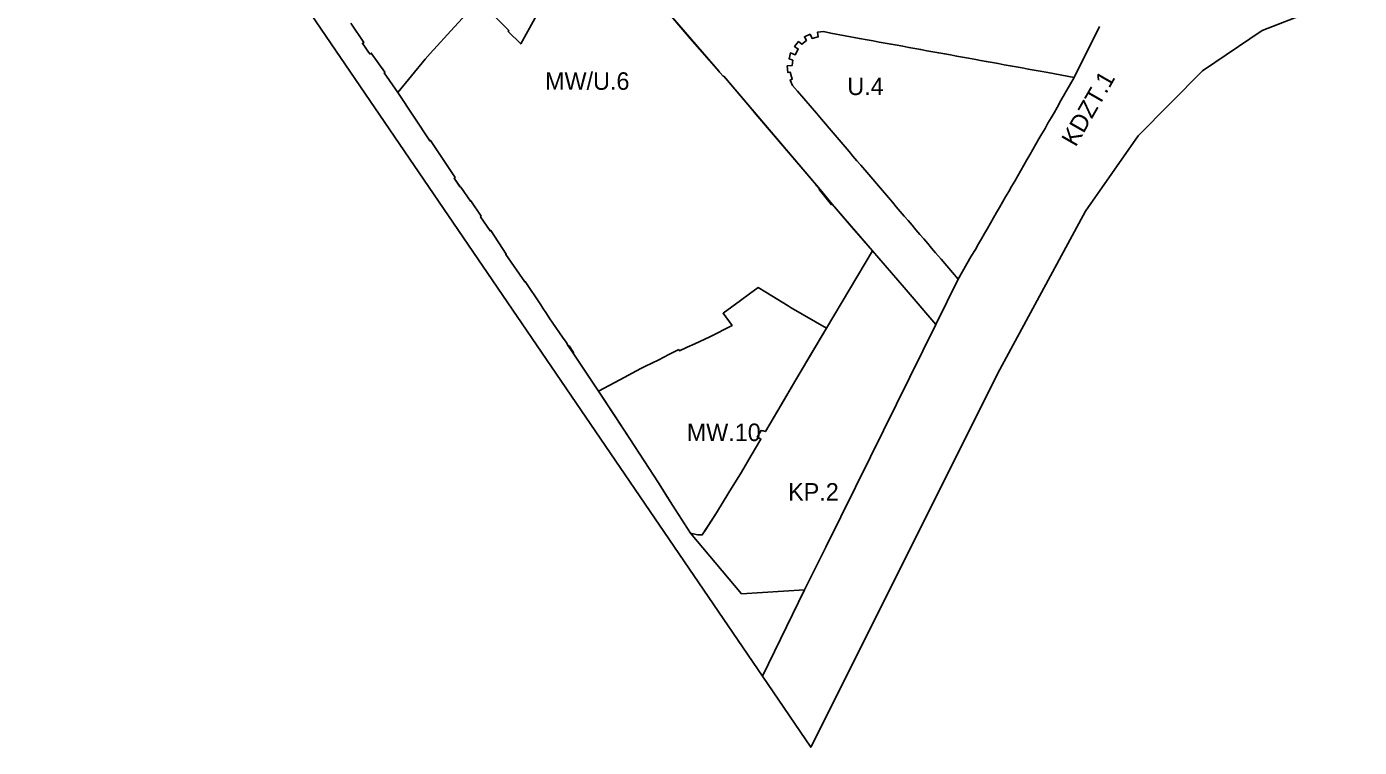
# Model space of a CAD drawing. Extents: x 7423893 to 7425332, y 5547241 to 5548246.
# Drawn here: x 7424259.3 to 7424640.4, y 5547241.4 to 5547447.3 of the extents above; entities that cross this region are included whole.
import ezdxf

# ---------------------------------------------------------------- set-up
doc = ezdxf.new("R2010")
doc.units = 0
for name, color, linetype in [('linie rozgraniczające', 7, 'Continuous'), ('obowiazujace linie zabudowy', 7, 'Continuous'), ('przeznaczenia terenów', 7, 'Continuous')]:
    doc.layers.add(name, color=color, linetype=linetype)

msp = doc.modelspace()

# ---------------------------------------------------------------- linework, layer by layer
at = {"layer": 'linie rozgraniczające'}
for p, q in [((7424566.05, 5547447.44), (7424558.82, 5547432.87)), ((7424525.63, 5547375.18), (7424519.23, 5547362.27)), ((7424469.69, 5547261.72), (7424469.69, 5547261.72))]:
    msp.add_line(p, q, dxfattribs=at)
for points in [[(7424259.33, 5547570.21), (7424469.69, 5547261.72)], [(7424469.69, 5547261.72), (7424483.52, 5547241.43), (7424537.6, 5547349.36), (7424562.07, 5547394.62), (7424577.11, 5547416.18), (7424595.5, 5547434.76), (7424612.59, 5547446.29), (7424626.63, 5547451.7), (7424635.53, 5547459.94), (7424639.81, 5547463.89), (7424640.36, 5547480.81)], [(7424415.66, 5547470.19), (7424413.19, 5547466.17), (7424409.66, 5547459.31), (7424406.13, 5547452.45), (7424400.58, 5547442.44), (7424397.01, 5547445.97), (7424397.17, 5547446.22), (7424388.59, 5547454.83), (7424381.66, 5547447.26)], [(7424501.13, 5547383.3), (7424489.66, 5547396.63), (7424486.16, 5547400.86), (7424485.17, 5547402.05), (7424467.84, 5547422.39), (7424466.57, 5547423.89), (7424458.65, 5547433.22), (7424458.53, 5547433.13), (7424457.55, 5547434.22), (7424457.44, 5547434.34), (7424457.28, 5547434.51), (7424440.89, 5547453.46)], [(7424351.98, 5547448.38), (7424355.74, 5547442.87), (7424355.32, 5547442.58), (7424355.74, 5547442.02), (7424357.09, 5547440.11), (7424357.53, 5547439.53), (7424357.87, 5547439.79), (7424361.77, 5547434.31), (7424361.56, 5547434.17), (7424365.41, 5547428.52), (7424374.58, 5547414.69), (7424374.81, 5547414.86), (7424381.84, 5547404.24), (7424381.53, 5547404.03), (7424383.1, 5547401.77), (7424383.24, 5547401.57), (7424383.3, 5547401.62), (7424383.42, 5547401.46), (7424386.19, 5547397.46), (7424386.34, 5547397.56), (7424389.26, 5547393.16), (7424389.05, 5547393.01), (7424391.85, 5547388.98), (7424392.05, 5547389.12), (7424396.45, 5547382.37), (7424396.31, 5547382.27), (7424401.76, 5547374.41), (7424401.9, 5547374.51), (7424406.33, 5547367.86), (7424406.92, 5547366.89), (7424407.95, 5547365.35), (7424408.77, 5547364.15), (7424409.79, 5547362.62), (7424410.64, 5547361.36), (7424411.66, 5547359.84), (7424412.5, 5547358.59), (7424413.54, 5547357.17), (7424414.16, 5547356.14), (7424415.61, 5547354.02), (7424422.85, 5547343.23), (7424431.82, 5547329.6), (7424439.96, 5547316.96), (7424444, 5547310.62), (7424447.4, 5547305.27), (7424449.09, 5547302.6), (7424463.74, 5547285.3)], [(7424381.66, 5547447.26), (7424374.72, 5547439.69), (7424373.27, 5547438.11), (7424369.34, 5547433.32), (7424365.41, 5547428.52)], [(7424501.13, 5547383.3), (7424494.58, 5547372.26), (7424488.04, 5547361.23), (7424479.29, 5547346.48), (7424470.55, 5547331.72), (7424469.94, 5547331.84), (7424469.33, 5547331.97), (7424468.78, 5547331.04), (7424468.23, 5547330.1), (7424468.74, 5547329.79), (7424469.25, 5547329.49), (7424466.46, 5547324.79), (7424463.67, 5547320.1), (7424460.13, 5547314.25), (7424456.59, 5547308.39), (7424455.07, 5547306.03), (7424453.55, 5547303.67), (7424452.5, 5547302.12), (7424451.2, 5547302.15), (7424449.88, 5547302.42), (7424449.09, 5547302.6)], [(7424501.13, 5547383.3), (7424510.18, 5547372.79), (7424519.23, 5547362.27), (7424500.59, 5547324.48), (7424487.87, 5547298.59), (7424481.73, 5547286.39), (7424463.74, 5547285.3)], [(7424488.04, 5547361.23), (7424477.93, 5547367.05), (7424477.05, 5547367.56), (7424470.64, 5547371.5), (7424468.5, 5547372.82), (7424465.99, 5547370.98), (7424463.47, 5547369.15), (7424458.44, 5547365.47), (7424461, 5547361.97), (7424454.7, 5547358.77), (7424450.33, 5547356.77), (7424448.15, 5547355.77), (7424445.97, 5547354.77), (7424445.84, 5547355.06)], [(7424445.84, 5547355.06), (7424442.96, 5547353.63), (7424440.08, 5547352.2), (7424438.06, 5547351.23), (7424436.04, 5547350.25), (7424434.91, 5547349.65), (7424428.88, 5547346.44), (7424422.85, 5547343.23)], [(7424469.69, 5547261.72), (7424481.73, 5547286.39)]]:
    msp.add_lwpolyline(points, dxfattribs=at)
msp.add_lwpolyline([(7424506.84, 5547397.21), (7424505.7, 5547398.54), (7424504.57, 5547399.86), (7424503.46, 5547401.16), (7424502.32, 5547402.49), (7424501.22, 5547403.78), (7424500.1, 5547405.1), (7424498.97, 5547406.42), (7424497.84, 5547407.75), (7424496.73, 5547409.05), (7424495.59, 5547410.38), (7424494.5, 5547411.67), (7424493.34, 5547413.02), (7424492.2, 5547414.36), (7424491.06, 5547415.69), (7424489.95, 5547416.99), (7424488.82, 5547418.31), (7424487.74, 5547419.58), (7424486.59, 5547420.92), (7424485.13, 5547422.67), (7424479.75, 5547428.95), (7424478.31, 5547430.5), (7424477.59, 5547432.07), (7424478.22, 5547432.31), (7424477.62, 5547434.36), (7424476.98, 5547434.23), (7424476.8, 5547436.12), (7424478.18, 5547436.23), (7424478.38, 5547437.74), (7424477.3, 5547438.17), (7424477.71, 5547439.83), (7424479.03, 5547439.3), (7424479.96, 5547440.93), (7424478.9, 5547441.73), (7424480.01, 5547443.1), (7424480.98, 5547442.35), (7424482.26, 5547443.42), (7424481.7, 5547444.46), (7424483.31, 5547445.2), (7424483.9, 5547443.97), (7424485.62, 5547444.44), (7424485.46, 5547445.81), (7424487.19, 5547445.95), (7424489.26, 5547445.48), (7424497.41, 5547443.94), (7424499.65, 5547443.58), (7424501.38, 5547443.26), (7424503.07, 5547442.96), (7424504.78, 5547442.65), (7424506.47, 5547442.34), (7424508.18, 5547442.04), (7424509.86, 5547441.74), (7424511.57, 5547441.43), (7424513.26, 5547441.12), (7424514.97, 5547440.8), (7424516.69, 5547440.49), (7424518.4, 5547440.18), (7424520.1, 5547439.87), (7424521.81, 5547439.56), (7424523.5, 5547439.26), (7424525.22, 5547438.95), (7424526.89, 5547438.64), (7424528.61, 5547438.33), (7424530.71, 5547437.95), (7424532.06, 5547437.7), (7424533.71, 5547437.41), (7424535.43, 5547437.1), (7424537.12, 5547436.79), (7424538.85, 5547436.47), (7424540.55, 5547436.17), (7424542.27, 5547435.85), (7424543.96, 5547435.55), (7424545.68, 5547435.24), (7424547.41, 5547434.92), (7424549.12, 5547434.61), (7424551.31, 5547434.22), (7424558.82, 5547432.87), (7424555.06, 5547426.23), (7424553.95, 5547424.27), (7424553.07, 5547422.74), (7424552.23, 5547421.28), (7424551.34, 5547419.73), (7424550.49, 5547418.28), (7424549.6, 5547416.73), (7424548.76, 5547415.27), (7424547.88, 5547413.73), (7424547.04, 5547412.27), (7424546.16, 5547410.74), (7424545.3, 5547409.26), (7424544.42, 5547407.73), (7424543.58, 5547406.27), (7424542.69, 5547404.73), (7424541.84, 5547403.25), (7424540.95, 5547401.71), (7424540.11, 5547400.25), (7424539.22, 5547398.72), (7424538.38, 5547397.24), (7424537.5, 5547395.72), (7424536.65, 5547394.26), (7424535.77, 5547392.72), (7424534.92, 5547391.25), (7424534.03, 5547389.71), (7424533.19, 5547388.25), (7424532.32, 5547386.74), (7424531.47, 5547385.26), (7424530.57, 5547383.7), (7424529.4, 5547381.73), (7424525.63, 5547375.18), (7424520.76, 5547380.92), (7424519.2, 5547382.71), (7424518.07, 5547384.04), (7424516.95, 5547385.35), (7424515.82, 5547386.68), (7424514.7, 5547387.98), (7424513.57, 5547389.3), (7424512.46, 5547390.61), (7424511.33, 5547391.94), (7424510.21, 5547393.24), (7424509.09, 5547394.56), (7424507.96, 5547395.88)], close=True, dxfattribs=at)
at = {"layer": 'obowiazujace linie zabudowy'}
for points in [[(7424456.59, 5547308.39), (7424460.13, 5547314.25), (7424463.67, 5547320.1), (7424466.46, 5547324.79), (7424469.25, 5547329.49), (7424468.74, 5547329.79), (7424468.23, 5547330.1), (7424469.33, 5547331.97), (7424470.55, 5547331.72), (7424474.92, 5547339.1), (7424479.29, 5547346.48), (7424483.67, 5547353.85), (7424488.04, 5547361.23), (7424494.58, 5547372.26), (7424501.13, 5547383.3), (7424495.4, 5547389.96), (7424489.66, 5547396.63), (7424489.47, 5547396.47), (7424485.98, 5547400.7), (7424485.88, 5547400.81), (7424485.98, 5547400.9), (7424485.05, 5547401.96), (7424485.17, 5547402.05), (7424458.65, 5547433.22), (7424458.53, 5547433.13), (7424457.55, 5547434.22), (7424457.44, 5547434.34), (7424457.28, 5547434.51), (7424449.08, 5547443.99), (7424440.89, 5547453.46)], [(7424351.98, 5547448.38), (7424355.74, 5547442.87), (7424355.32, 5547442.58), (7424355.74, 5547442.02), (7424357.09, 5547440.11), (7424357.53, 5547439.53), (7424357.87, 5547439.79), (7424361.77, 5547434.31), (7424361.56, 5547434.17), (7424365.41, 5547428.52), (7424374.58, 5547414.69), (7424374.81, 5547414.86)], [(7424374.81, 5547414.86), (7424381.84, 5547404.24), (7424381.53, 5547404.03), (7424383.24, 5547401.57), (7424383.3, 5547401.62), (7424383.42, 5547401.46), (7424386.19, 5547397.46), (7424386.34, 5547397.56), (7424389.26, 5547393.16), (7424389.05, 5547393.01), (7424391.85, 5547388.98), (7424392.05, 5547389.12), (7424396.45, 5547382.37), (7424396.31, 5547382.27), (7424401.76, 5547374.41), (7424401.9, 5547374.51), (7424406.33, 5547367.86), (7424406.92, 5547366.89), (7424407.95, 5547365.35), (7424408.77, 5547364.15), (7424409.79, 5547362.62), (7424410.64, 5547361.36), (7424411.66, 5547359.84), (7424412.5, 5547358.59), (7424413.54, 5547357.17), (7424414.16, 5547356.14), (7424414.4, 5547356.14), (7424415.69, 5547354.23), (7424415.61, 5547354.02), (7424422.85, 5547343.23), (7424427.33, 5547336.42), (7424431.82, 5547329.6), (7424435.89, 5547323.28), (7424439.96, 5547316.96), (7424441.98, 5547313.79), (7424444, 5547310.62), (7424447.4, 5547305.27), (7424449.09, 5547302.6), (7424449.88, 5547302.42), (7424451.2, 5547302.15), (7424452.5, 5547302.12), (7424456.59, 5547308.39)]]:
    msp.add_lwpolyline(points, dxfattribs=at)
msp.add_lwpolyline([(7424506.84, 5547397.21), (7424507.96, 5547395.88), (7424509.09, 5547394.56), (7424510.21, 5547393.24), (7424511.33, 5547391.94), (7424512.46, 5547390.61), (7424513.57, 5547389.3), (7424514.7, 5547387.98), (7424515.82, 5547386.68), (7424516.95, 5547385.35), (7424518.07, 5547384.04), (7424519.2, 5547382.71), (7424520.76, 5547380.92), (7424525.63, 5547375.18), (7424529.4, 5547381.73), (7424530.57, 5547383.7), (7424531.47, 5547385.26), (7424532.32, 5547386.74), (7424533.19, 5547388.25), (7424534.03, 5547389.71), (7424534.92, 5547391.25), (7424535.77, 5547392.72), (7424536.65, 5547394.26), (7424537.5, 5547395.72), (7424538.38, 5547397.24), (7424539.22, 5547398.72), (7424540.11, 5547400.25), (7424540.95, 5547401.71), (7424541.84, 5547403.25), (7424542.69, 5547404.73), (7424543.58, 5547406.27), (7424544.42, 5547407.73), (7424545.3, 5547409.26), (7424546.16, 5547410.74), (7424547.04, 5547412.27), (7424547.88, 5547413.73), (7424548.76, 5547415.27), (7424549.6, 5547416.73), (7424550.49, 5547418.28), (7424551.34, 5547419.73), (7424552.23, 5547421.28), (7424553.07, 5547422.74), (7424553.95, 5547424.27), (7424555.06, 5547426.23), (7424558.82, 5547432.87), (7424551.31, 5547434.22), (7424549.12, 5547434.61), (7424547.41, 5547434.92), (7424545.68, 5547435.24), (7424543.96, 5547435.55), (7424542.27, 5547435.85), (7424540.55, 5547436.17), (7424538.85, 5547436.47), (7424537.12, 5547436.79), (7424535.43, 5547437.1), (7424533.71, 5547437.41), (7424532.06, 5547437.7), (7424530.71, 5547437.95), (7424528.61, 5547438.33), (7424526.89, 5547438.64), (7424525.22, 5547438.95), (7424523.5, 5547439.26), (7424521.81, 5547439.56), (7424520.1, 5547439.87), (7424518.4, 5547440.18), (7424516.69, 5547440.49), (7424514.97, 5547440.8), (7424513.26, 5547441.12), (7424511.57, 5547441.43), (7424509.86, 5547441.74), (7424508.18, 5547442.04), (7424506.47, 5547442.34), (7424504.78, 5547442.65), (7424503.07, 5547442.96), (7424501.38, 5547443.26), (7424499.65, 5547443.58), (7424497.41, 5547443.94), (7424489.26, 5547445.48), (7424487.19, 5547445.95), (7424485.46, 5547445.81), (7424485.62, 5547444.44), (7424483.9, 5547443.97), (7424483.31, 5547445.2), (7424481.7, 5547444.46), (7424482.26, 5547443.42), (7424480.98, 5547442.35), (7424480.01, 5547443.1), (7424478.9, 5547441.73), (7424479.96, 5547440.93), (7424479.03, 5547439.3), (7424477.71, 5547439.83), (7424477.3, 5547438.17), (7424478.38, 5547437.74), (7424478.18, 5547436.23), (7424476.8, 5547436.12), (7424476.98, 5547434.23), (7424477.62, 5547434.36), (7424478.22, 5547432.31), (7424477.59, 5547432.07), (7424478.31, 5547430.5), (7424479.75, 5547428.95), (7424485.13, 5547422.67), (7424486.59, 5547420.92), (7424487.74, 5547419.58), (7424488.82, 5547418.31), (7424489.95, 5547416.99), (7424491.06, 5547415.69), (7424492.2, 5547414.36), (7424493.34, 5547413.02), (7424494.5, 5547411.67), (7424495.59, 5547410.38), (7424496.73, 5547409.05), (7424497.84, 5547407.75), (7424498.97, 5547406.42), (7424500.1, 5547405.1), (7424501.22, 5547403.78), (7424502.32, 5547402.49), (7424503.46, 5547401.16), (7424504.57, 5547399.86), (7424505.7, 5547398.54)], close=True, dxfattribs=at)

# ---------------------------------------------------------------- texts
at = {"layer": 'przeznaczenia terenów'}
for s, p in [('MW/U.6', (7424407.54, 5547429.31)), ('U.4', (7424493.96, 5547427.81)), ('MW.10', (7424448.05, 5547328.94)), ('KP.2', (7424477.03, 5547311.93))]:
    msp.add_text(s, height=5, dxfattribs=at).set_placement(p)
msp.add_text('KDZT.1', height=5, rotation=60.1757, dxfattribs=at).set_placement((7424559.26, 5547412.76))

doc.saveas('drawing.dxf')
